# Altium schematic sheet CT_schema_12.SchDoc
size 146 x 119 mm
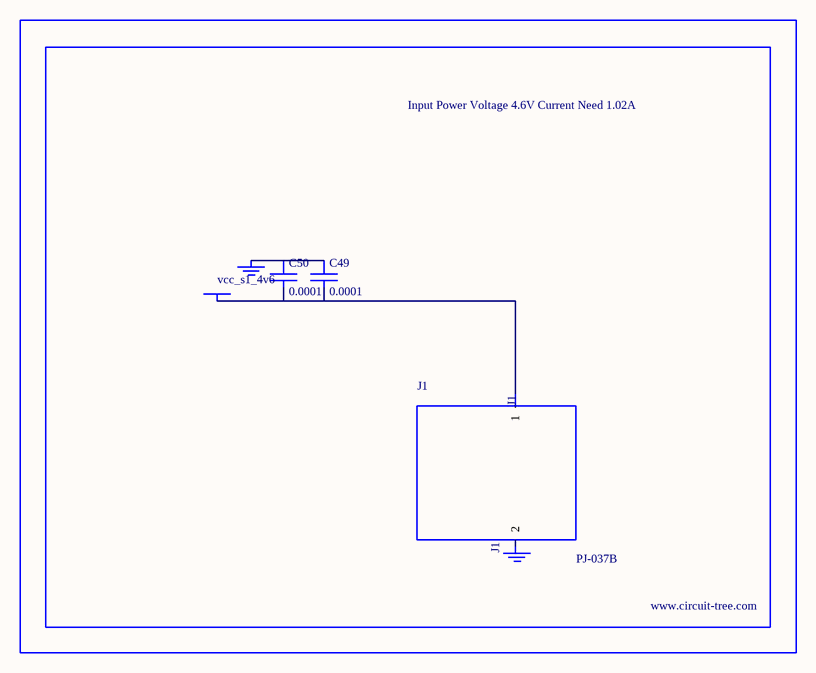
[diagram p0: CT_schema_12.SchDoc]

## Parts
BORDER11  (no value)
C49  0.0001  [EXV-9H]
C50  0.0001  [EXV-9H]
GND_INSTANCE_11_0  (no value)
GND_INSTANCE_11_1  (no value)
J1  PJ-037B  [PJ-037B_PACKAGE]
POWER_INSTANCE_11_0  vcc_s1_4v6

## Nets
NetC49_1: C49.1 C50.1 GND_INSTANCE_11_0.0(GND)
NetC49_2: C49.2 C50.2 J1.1 POWER_INSTANCE_11_0.0(PWR)

Not connected (* = marked no-connect by the designer): GND_INSTANCE_11_1 0(GND); J1 2

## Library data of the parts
BORDER11 = BORDER_PAGE11
C49 C50 = EDK107M035A9HAA
GND_INSTANCE_11_0 GND_INSTANCE_11_1 = GND
POWER_INSTANCE_11_0 = PWR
